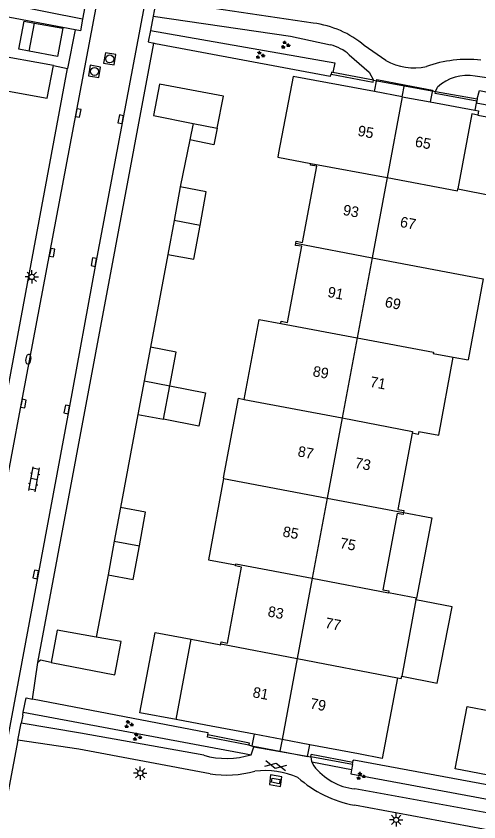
# Model space of a CAD drawing. Extents: x 124000 to 128010, y 398999 to 403000.
# Drawn here: x 126814.4 to 126858.2, y 399368.7 to 399444.8 of the extents above; entities that cross this region are included whole.
import ezdxf

# ---------------------------------------------------------------- set-up
doc = ezdxf.new("R2010")
doc.units = 0
for name, color, linetype in [('gg-afsc-hekwerk', 7, 'Continuous'), ('gg-afsc-muur', 7, 'Continuous'), ('gg-anno-huisnummerreeks BGT', 7, 'Continuous'), ('gg-bbg-bijgebouw', 7, 'Continuous'), ('gg-bbg-gedigitaliseerde bijgebouw', 7, 'Continuous'), ('gg-bbg-hoofdgebouw', 7, 'Continuous'), ('gg-bbg-luifel en loopbrug', 7, 'Continuous'), ('gg-bbg-tussenscheiding', 7, 'Continuous'), ('gg-knt-verharding', 7, 'Continuous'), ('gt-grn-groengrens', 7, 'Continuous'), ('gt-grn-vlakafsluiter', 7, 'Continuous'), ('gt-symb-brandkraan', 7, 'Continuous'), ('gt-symb-gesloten verharding', 7, 'Continuous'), ('gt-symb-groenvak', 7, 'Continuous'), ('gt-symb-klinker verharding', 7, 'Continuous'), ('gt-symb-kolk', 7, 'Continuous'), ('gt-symb-kolk center center', 7, 'Continuous'), ('gt-symb-lichtmast', 7, 'Continuous'), ('gt-symb-rioolschacht', 7, 'Continuous')]:
    doc.layers.add(name, color=color, linetype=linetype)

# ---------------------------------------------------------------- blocks, each defined once
blk = doc.blocks.new('gt0-GRVAK')
at = {"layer": 'gt-symb-groenvak'}
for p, q in [((-0.11, 0.189), (-0.228, 0.24)), ((-0.182, 0.153), (0.088, 0.153)), ((-0.091, 0.211), (-0.156, 0.322)), ((-0.047, 0.214), (-0.047, 0.393)), ((-0.004, 0.211), (0.061, 0.322)), ((0.015, 0.189), (0.133, 0.24)), ((0.262, -0.052), (0.197, 0.059)), ((0.305, -0.049), (0.305, 0.13)), ((0.349, -0.052), (0.414, 0.059)), ((-0.245, -0.228), (-0.363, -0.177)), ((-0.318, -0.264), (-0.047, -0.264)), ((-0.226, -0.206), (-0.291, -0.095)), ((-0.183, -0.203), (-0.183, -0.024)), ((-0.139, -0.206), (-0.074, -0.095)), ((-0.12, -0.228), (-0.002, -0.177)), ((0.243, -0.074), (0.125, -0.023)), ((0.17, -0.11), (0.441, -0.11)), ((0.368, -0.074), (0.486, -0.023))]:
    blk.add_line(p, q, dxfattribs=at)
blk = doc.blocks.new('gt0-RS')
at = {"layer": 'gt-symb-rioolschacht'}
blk.add_lwpolyline([(-0.5, -0.5), (0.5, -0.5), (0.5, 0.5), (-0.5, 0.5)], close=True, dxfattribs=at)
blk.add_circle((0, 0), 0.375, dxfattribs=at)
blk = doc.blocks.new('gt0-KOLK')
at = {"layer": 'gt-symb-kolk'}
blk.add_lwpolyline([(0, 0), (0.375, 0), (0.375, 0.4), (-0.375, 0.4), (-0.375, 0), (0, 0)], dxfattribs=at)
blk = doc.blocks.new('gt0-BR')
at = {"layer": 'gt-symb-brandkraan'}
for centre, radius, start, end in [((-0.244, 0), 0.206, 107.56694, 252.43307), ((0.599, -2.664), 3, 106.89205, 107.56694), ((0, -0.691), 0.938, 73.10799, 106.89205), ((-0.599, -2.664), 3, 72.43309, 73.10799), ((0.244, 0), 0.206, 287.56695, 72.43309), ((0.599, 2.664), 3, 252.43307, 253.10797), ((0, 0.691), 0.938, 253.10797, 286.89206), ((-0.599, 2.664), 3, 286.89206, 287.56695)]:
    blk.add_arc(centre, radius, start, end, dxfattribs=at)
blk = doc.blocks.new('gt0-LMAST')
at = {"layer": 'gt-symb-lichtmast'}
for p, q in [((-0.182, 0.173), (-0.447, 0.438)), ((-0.005, 0.246), (-0.005, 0.621)), ((0.172, 0.173), (0.437, 0.438)), ((-0.255, -0.004), (-0.63, -0.004)), ((-0.182, -0.181), (-0.447, -0.446)), ((-0.005, -0.254), (-0.005, -0.629)), ((0.437, -0.446), (0.172, -0.181)), ((0.245, -0.004), (0.62, -0.004))]:
    blk.add_line(p, q, dxfattribs=at)
blk.add_circle((-0.005, -0.004), 0.25, dxfattribs=at)
blk = doc.blocks.new('gt0-KL1')
at = {"layer": 'gt-symb-klinker verharding'}
for p, q in [((-1.15, 0.3), (1.15, 0.3)), ((-1, -0.3), (-1, 0.3)), ((-0.5, 0.3), (-0.5, 0.45)), ((0, -0.3), (0, 0.3)), ((0.5, 0.3), (0.5, 0.45)), ((1, -0.3), (1, 0.3)), ((-1.15, -0.3), (1.15, -0.3)), ((-0.5, -0.45), (-0.5, -0.3)), ((0.5, -0.45), (0.5, -0.3))]:
    blk.add_line(p, q, dxfattribs=at)
blk = doc.blocks.new('gt0-KOLKCC')
at = {"layer": 'gt-symb-kolk center center'}
blk.add_lwpolyline([(-0.375, 0.2), (0.375, 0.2), (0.375, -0.2), (-0.375, -0.2)], close=True, dxfattribs=at)
blk = doc.blocks.new('gt0-GESVH1')
at = {"layer": 'gt-symb-gesloten verharding'}
for p, q in [((-0.992, -0.261), (0.008, 0.239)), ((0.008, -0.261), (-0.992, 0.239)), ((0.008, 0.239), (1.008, -0.261)), ((1.008, 0.239), (0.008, -0.261))]:
    blk.add_line(p, q, dxfattribs=at)

msp = doc.modelspace()

# ---------------------------------------------------------------- linework, layer by layer
at = {"layer": 'gg-afsc-hekwerk'}
for p, q in [((126820.026, 399443.528), (126803.416, 399446.654)), ((126820.026, 399443.528), (126819.288, 399439.86)), ((126844.111, 399439.101), (126827.619, 399442.195)), ((126817.958, 399440.148), (126819.288, 399439.86)), ((126857.916, 399436.59), (126857.791, 399435.917)), ((126874.745, 399433.479), (126857.916, 399436.59)), ((126815.983, 399380.296), (126816.503, 399383.757)), ((126832.566, 399377.128), (126815.983, 399380.296)), ((126862.844, 399371.481), (126846.35, 399374.538))]:
    msp.add_line(p, q, dxfattribs=at)
msp.add_lwpolyline([(126817.745, 399383.756), (126816.743, 399383.971), (126816.503, 399383.757)], dxfattribs=at)
at = {"layer": 'gg-afsc-muur'}
for p, q in [((126848.224, 399438.763), (126844.388, 399439.499)), ((126854.083, 399437.706), (126858.03, 399436.986)), ((126858.03, 399436.986), (126857.994, 399436.789)), ((126830.851, 399433.115), (126829.955, 399428.676)), ((126828.779, 399422.309), (126827.151, 399413.539)), ((126825.948, 399407.185), (126824.306, 399398.398)), ((126823.127, 399392.05), (126822.02, 399386.159)), ((126832.518, 399376.72), (126832.557, 399376.916)), ((126836.488, 399376.149), (126832.557, 399376.916)), ((126836.45, 399375.953), (126832.518, 399376.72)), ((126836.45, 399375.953), (126836.488, 399376.149)), ((126842.281, 399374.864), (126842.318, 399375.06)), ((126846.232, 399374.128), (126842.281, 399374.864)), ((126846.268, 399374.325), (126842.318, 399375.06)), ((126846.232, 399374.128), (126846.268, 399374.325))]:
    msp.add_line(p, q, dxfattribs=at)
for points in [[(126844.388, 399439.499), (126844.251, 399439.525), (126844.213, 399439.329)], [(126844.213, 399439.329), (126848.186, 399438.567), (126848.224, 399438.763)], [(126857.994, 399436.789), (126854.047, 399437.509), (126854.083, 399437.706)]]:
    msp.add_lwpolyline(points, dxfattribs=at)
at = {"layer": 'gg-bbg-bijgebouw'}
for p, q in [((126827.434, 399435.41), (126831.167, 399434.677)), ((126829.955, 399428.676), (126829.367, 399425.495)), ((126829.367, 399425.495), (126828.779, 399422.309)), ((126827.151, 399413.539), (126826.549, 399410.359)), ((126826.549, 399410.359), (126825.948, 399407.185)), ((126828.356, 399406.729), (126828.956, 399409.903)), ((126825.948, 399407.185), (126828.356, 399406.729)), ((126824.306, 399398.398), (126823.717, 399395.226)), ((126823.717, 399395.226), (126823.127, 399392.05))]:
    msp.add_line(p, q, dxfattribs=at)
for points in [[(126817.958, 399440.148), (126811.994, 399441.217), (126811.41, 399438.123), (126813.727, 399437.718)], [(126813.727, 399437.718), (126817.385, 399437.058), (126817.958, 399440.148)], [(126833.439, 399434.231), (126834.031, 399437.246), (126827.98, 399438.384), (126827.434, 399435.41)], [(126831.821, 399425.042), (126832.409, 399428.222), (126829.955, 399428.676)], [(126828.779, 399422.309), (126831.232, 399421.856), (126831.821, 399425.042)], [(126828.956, 399409.903), (126829.558, 399413.084), (126827.151, 399413.539)], [(126826.091, 399394.785), (126826.68, 399397.958), (126824.306, 399398.398)], [(126823.127, 399392.05), (126825.502, 399391.609), (126826.091, 399394.785)], [(126822.02, 399386.159), (126818.335, 399386.827), (126817.745, 399383.756)], [(126817.745, 399383.756), (126823.781, 399382.598), (126824.355, 399385.735), (126822.02, 399386.159)], [(126862.012, 399372.561), (126855.952, 399373.719), (126857.071, 399379.611), (126859.366, 399379.17)]]:
    msp.add_lwpolyline(points, dxfattribs=at)
at = {"layer": 'gg-bbg-gedigitaliseerde bijgebouw'}
for p, q in [((126815.688, 399441.486), (126816.188, 399444.158)), ((126816.188, 399444.158), (126818.859, 399443.658)), ((126831.167, 399434.677), (126830.851, 399433.115))]:
    msp.add_line(p, q, dxfattribs=at)
for points in [[(126818.859, 399443.658), (126818.359, 399440.986), (126815.688, 399441.486)], [(126833.439, 399434.231), (126833.132, 399432.667), (126830.851, 399433.115)]]:
    msp.add_lwpolyline(points, dxfattribs=at)
at = {"layer": 'gg-bbg-hoofdgebouw'}
for p, q in [((126848.305, 399437.69), (126840.638, 399439.12)), ((126850.944, 399437.198), (126848.305, 399437.69)), ((126850.944, 399437.198), (126853.582, 399436.704)), ((126853.582, 399436.704), (126857.791, 399435.917)), ((126856.203, 399428.493), (126859.515, 399427.848)), ((126858.576, 399420.007), (126857.181, 399412.345)), ((126855.75, 399412.61), (126857.181, 399412.345)), ((126834.049, 399401.214), (126834.034, 399401.135)), ((126852.271, 399389.851), (126849.638, 399390.343)), ((126852.236, 399389.665), (126852.271, 399389.851)), ((126852.236, 399389.665), (126850.893, 399382.473)), ((126829.581, 399378.373), (126830.999, 399385.95)), ((126833.793, 399385.518), (126833.828, 399385.705)), ((126832.359, 399377.853), (126829.581, 399378.373)), ((126836.937, 399376.99), (126832.359, 399377.853)), ((126839.575, 399376.493), (126836.937, 399376.99)), ((126842.212, 399375.996), (126839.575, 399376.493)), ((126846.793, 399375.132), (126842.212, 399375.996))]:
    msp.add_line(p, q, dxfattribs=at)
for points in [[(126840.638, 399439.12), (126839.256, 399431.902), (126839.176, 399431.48), (126842.283, 399430.884)], [(126858.09, 399435.47), (126857.518, 399435.592), (126856.203, 399428.493)], [(126857.791, 399435.917), (126858.15, 399435.85), (126858.09, 399435.47)], [(126840.877, 399423.354), (126840.904, 399423.559), (126841.507, 399423.422), (126842.853, 399430.635), (126842.259, 399430.721), (126842.283, 399430.884)], [(126839.458, 399415.794), (126839.497, 399416.011), (126840.086, 399415.859), (126841.446, 399423.078), (126840.851, 399423.156), (126840.877, 399423.354)], [(126836.009, 399408.614), (126837.414, 399416.168), (126839.458, 399415.794)], [(126852.491, 399405.572), (126854.384, 399405.222), (126855.75, 399412.61)], [(126834.049, 399401.214), (126835.451, 399408.718), (126836.009, 399408.614)], [(126851.874, 399405.406), (126850.516, 399398.225), (126851.087, 399398.123), (126851.054, 399397.939)], [(126852.491, 399405.572), (126852.435, 399405.286), (126851.874, 399405.406)], [(126834.034, 399401.135), (126832.616, 399393.447), (126835.191, 399392.972)], [(126851.054, 399397.939), (126851.019, 399397.742), (126850.452, 399397.846), (126849.11, 399390.638), (126849.672, 399390.542), (126849.638, 399390.343)], [(126833.828, 399385.705), (126834.411, 399385.583), (126835.754, 399392.777), (126835.175, 399392.889), (126835.191, 399392.972)], [(126830.999, 399385.95), (126833.777, 399385.43), (126833.793, 399385.518)], [(126850.479, 399382.319), (126849.043, 399374.708), (126846.793, 399375.132)], [(126850.479, 399382.319), (126850.847, 399382.245), (126850.893, 399382.473)]]:
    msp.add_lwpolyline(points, dxfattribs=at)
at = {"layer": 'gg-bbg-luifel en loopbrug'}
for p, q in [((126850.944, 399437.198), (126851.164, 399438.319)), ((126839.575, 399376.493), (126839.361, 399375.371))]:
    msp.add_line(p, q, dxfattribs=at)
for points in [[(126815.688, 399441.486), (126814.688, 399441.674), (126815.188, 399444.345), (126816.188, 399444.158)], [(126848.305, 399437.69), (126848.529, 399438.835), (126851.164, 399438.319)], [(126851.164, 399438.319), (126853.798, 399437.802), (126853.582, 399436.704)], [(126858.09, 399435.47), (126860.832, 399434.962), (126859.515, 399427.848)], [(126828.956, 399409.903), (126832.327, 399409.241), (126831.705, 399406.071), (126828.356, 399406.729)], [(126851.054, 399397.939), (126853.744, 399397.415), (126852.271, 399389.851)], [(126850.893, 399382.473), (126854.251, 399381.805), (126855.669, 399389.012), (126852.236, 399389.665)], [(126829.581, 399378.373), (126826.142, 399379.021), (126827.569, 399386.596), (126830.999, 399385.95)], [(126836.937, 399376.99), (126836.723, 399375.876), (126839.361, 399375.371)], [(126839.361, 399375.371), (126841.997, 399374.867), (126842.212, 399375.996)]]:
    msp.add_lwpolyline(points, dxfattribs=at)
at = {"layer": 'gg-bbg-tussenscheiding'}
for p, q in [((126850.944, 399437.198), (126849.513, 399429.557)), ((126831.167, 399434.677), (126833.439, 399434.231)), ((126842.283, 399430.884), (126849.513, 399429.557)), ((126849.513, 399429.557), (126848.096, 399421.989)), ((126831.821, 399425.042), (126829.367, 399425.495)), ((126840.877, 399423.354), (126848.096, 399421.989)), ((126848.096, 399421.989), (126846.682, 399414.439)), ((126848.096, 399421.989), (126858.576, 399420.007)), ((126839.458, 399415.794), (126846.682, 399414.439)), ((126846.682, 399414.439), (126845.262, 399406.86)), ((126826.549, 399410.359), (126828.956, 399409.903)), ((126836.009, 399408.614), (126845.262, 399406.86)), ((126845.262, 399406.86), (126843.845, 399399.295)), ((126834.034, 399401.135), (126843.845, 399399.295)), ((126843.845, 399399.295), (126842.426, 399391.719)), ((126843.845, 399399.295), (126851.054, 399397.939)), ((126823.717, 399395.226), (126826.091, 399394.785)), ((126842.426, 399391.719), (126841.009, 399384.151)), ((126842.426, 399391.719), (126849.638, 399390.343)), ((126833.793, 399385.518), (126841.009, 399384.151)), ((126841.009, 399384.151), (126839.575, 399376.493)), ((126841.009, 399384.151), (126850.479, 399382.319))]:
    msp.add_line(p, q, dxfattribs=at)
for points in [[(126849.513, 399429.557), (126856.168, 399428.304), (126856.203, 399428.493)], [(126846.682, 399414.439), (126853.893, 399413.064), (126853.873, 399412.957), (126855.75, 399412.61)], [(126845.262, 399406.86), (126851.909, 399405.59), (126851.874, 399405.406)], [(126835.191, 399392.972), (126835.213, 399393.085), (126842.426, 399391.719)]]:
    msp.add_lwpolyline(points, dxfattribs=at)
at = {"layer": 'gg-knt-verharding'}
for p, q in [((126821.038, 399446.191), (126820.727, 399444.538)), ((126827.684, 399446.343), (126827.392, 399444.795)), ((126842.532, 399444.147), (126828.915, 399446.161)), ((126827.392, 399444.795), (126827.137, 399443.44)), ((126816.503, 399383.757), (126827.444, 399442.255)), ((126849.376, 399440.607), (126847.346, 399442.046)), ((126811.957, 399400.528), (126819.288, 399439.86)), ((126848.224, 399438.763), (126854.083, 399437.706)), ((126854.083, 399437.706), (126854.273, 399438.092)), ((126815.068, 399378.794), (126814.922, 399378.024)), ((126815.068, 399378.794), (126815.12, 399379.07)), ((126814.618, 399376.418), (126814.922, 399378.024)), ((126814.618, 399376.418), (126813.286, 399369.399)), ((126836.647, 399375.054), (126836.904, 399375.79)), ((126836.904, 399375.79), (126842.281, 399374.864)), ((126842.391, 399374.335), (126842.566, 399373.998)), ((126863.093, 399368.791), (126846.447, 399371.813)), ((126862.797, 399367.223), (126846.411, 399370.27))]:
    msp.add_line(p, q, dxfattribs=at)
for points in [[(126808.081, 399371.666), (126814.936, 399408.253), (126822.833, 399450.006), (126832.134, 399500)], [(126836.701, 399500), (126832.374, 399476.902), (126829.81, 399462.975), (126827.176, 399449.222), (126826.994, 399448.111), (126821.981, 399421.546), (126819.42, 399407.629), (126812.345, 399369.809)], [(126827.392, 399444.795), (126840.381, 399442.92), (126844.159, 399442.089)], [(126820.727, 399444.538), (126820.519, 399443.429), (126820.026, 399443.528)], [(126827.137, 399443.44), (126826.936, 399442.372), (126827.444, 399442.255)], [(126845.925, 399441.168), (126847.816, 399439.509), (126848.224, 399438.763)], [(126875.482, 399435.293), (126870.794, 399436.177), (126859.811, 399438.871), (126857.83, 399439.141)], [(126815.12, 399379.07), (126815.375, 399380.412), (126815.983, 399380.296)], [(126832.176, 399374.999), (126820.53, 399377.079), (126814.922, 399378.024)], [(126832.768, 399373.246), (126820.367, 399375.575), (126814.618, 399376.418)], [(126842.281, 399374.864), (126842.353, 399374.409), (126842.391, 399374.335)], [(126838.497, 399373.156), (126838.387, 399372.232), (126839.445, 399372.048), (126839.544, 399372.968), (126838.497, 399373.156)]]:
    msp.add_lwpolyline(points, dxfattribs=at)
for centre, radius, start, end in [((126841.343, 399434.857), 9.366, 50.13766, 82.70602), ((126843.142, 399437.986), 4.227, 48.83153, 76.08281), ((126852.069, 399445.563), 5.64, 241.4815, 281.75753), ((126857.106, 399429.353), 11.373, 83.62525, 109.99187), ((126857.092, 399435.087), 4.121, 79.68958, 133.1732), ((126834.319, 399382.54), 7.84, 254.13519, 287.27439), ((126847.126, 399377.558), 5.784, 217.97796, 263.26308), ((126834.313, 399383.795), 10.661, 261.66989, 284.68977), ((126838.036, 399366.258), 7.296, 65.41057, 98.03664), ((126848.588, 399381.45), 11.39, 228.70832, 258.98007)]:
    msp.add_arc(centre, radius, start, end, dxfattribs=at)
at = {"layer": 'gt-grn-groengrens'}
for p, q in [((126815.12, 399379.07), (126836.039, 399375.158)), ((126836.039, 399375.158), (126836.647, 399375.054)), ((126846.142, 399373.636), (126842.391, 399374.335)), ((126846.232, 399374.128), (126846.142, 399373.636)), ((126857.804, 399371.062), (126863.325, 399370.02))]:
    msp.add_line(p, q, dxfattribs=at)
for points in [[(126820.727, 399444.538), (126803.679, 399447.938), (126803.513, 399447.17)], [(126827.137, 399443.44), (126844.563, 399440.411), (126844.388, 399439.499)], [(126858.03, 399436.986), (126858.234, 399437.799), (126870.014, 399435.35), (126875.007, 399434.4), (126874.834, 399433.463), (126874.745, 399433.479)], [(126846.142, 399373.636), (126846.073, 399373.256), (126857.804, 399371.062)]]:
    msp.add_lwpolyline(points, dxfattribs=at)
at = {"layer": 'gt-grn-vlakafsluiter'}
for p, q in [((126827.619, 399442.195), (126827.444, 399442.255)), ((126844.111, 399439.101), (126844.213, 399439.329)), ((126857.994, 399436.789), (126857.916, 399436.59)), ((126836.904, 399375.79), (126836.45, 399375.953))]:
    msp.add_line(p, q, dxfattribs=at)
for points in [[(126832.557, 399376.916), (126832.597, 399377.122), (126832.566, 399377.128)], [(126846.268, 399374.325), (126846.309, 399374.546), (126846.35, 399374.538)]]:
    msp.add_lwpolyline(points, dxfattribs=at)

# ---------------------------------------------------------------- block references
at = {"layer": 'gt-symb-brandkraan', "rotation": 81.43241009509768}
msp.add_blockref('gt0-BR', (126815.597, 399412.4), dxfattribs=at)
at = {"layer": 'gt-symb-gesloten verharding', "rotation": -12.354826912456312}
msp.add_blockref('gt0-GESVH1', (126838.965, 399374.015), dxfattribs=at)
at = {"layer": 'gt-symb-groenvak'}
for p in [(126839.873, 399442.094), (126837.491, 399441.119), (126825.074, 399377.918), (126825.862, 399376.723), (126847.005, 399373.032)]:
    msp.add_blockref('gt0-GRVAK', p, dxfattribs=at)
at = {"layer": 'gt-symb-klinker verharding', "rotation": 79.39794170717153}
msp.add_blockref('gt0-KL1', (126816.143, 399401.07), dxfattribs=at)
at = {"layer": 'gt-symb-kolk'}
for p, rotation in [((126820.114, 399435.695), -100.65836150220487), ((126824.527, 399435.035), 79.39794170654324), ((126817.647, 399422.503), -100.60205829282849), ((126821.981, 399421.546), 79.4542656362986), ((126814.936, 399408.253), -100.65836150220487), ((126819.42, 399407.629), 79.39794170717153), ((126816.489, 399392.046), 79.4542656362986)]:
    msp.add_blockref('gt0-KOLK', p, dxfattribs=dict(at, rotation=rotation))
at = {"layer": 'gt-symb-kolk center center', "rotation": 169.45426563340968}
msp.add_blockref('gt0-KOLKCC', (126838.985, 399372.575), dxfattribs=at)
at = {"layer": 'gt-symb-lichtmast'}
for p in [(126815.921, 399420.182), (126826.18, 399373.315), (126850.365, 399368.9)]:
    msp.add_blockref('gt0-LMAST', p, dxfattribs=at)
at = {"layer": 'gt-symb-rioolschacht'}
for p, rotation in [((126823.287, 399440.771), 80.4434723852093), ((126821.851, 399439.586), 80.44347238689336)]:
    msp.add_blockref('gt0-RS', p, dxfattribs=dict(at, rotation=rotation))

# ---------------------------------------------------------------- texts
at = {"layer": 'gg-anno-huisnummerreeks BGT'}
for s, rotation, p in [('95', 349.4, (126846.672, 399433.52)), ('65', 349.5, (126852.086, 399432.493)), ('93', 349.5, (126845.275, 399426.045)), ('67', 349.3, (126850.666, 399424.914)), ('91', 349.3, (126843.825, 399418.293)), ('69', 349.3, (126849.237, 399417.349)), ('89', 349.4, (126842.418, 399410.814)), ('71', 349.5, (126847.829, 399409.812)), ('87', 349.4, (126840.997, 399403.242)), ('73', 349.3, (126846.399, 399402.161)), ('85', 349.4, (126839.576, 399395.672)), ('75', 349.5, (126844.985, 399394.582)), ('83', 349.4, (126838.164, 399388.125)), ('77', 349.4, (126843.58, 399387.041)), ('81', 349.4, (126836.74, 399380.493)), ('79', 349.4, (126842.162, 399379.434))]:
    msp.add_text(s, height=1, rotation=rotation, dxfattribs=at).set_placement(p)

doc.saveas('drawing.dxf')
